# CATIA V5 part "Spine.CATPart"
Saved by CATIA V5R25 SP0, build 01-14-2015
Part number: Part1
Bounding box of the stored display mesh (mm): x 97.05 to 179.832, y -8.213 to 8.213, z -51.727 to 9.114
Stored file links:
  E:\cadcim\GSD_cat_v5-6r2014\Part_files\Spine.CATPart
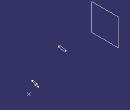
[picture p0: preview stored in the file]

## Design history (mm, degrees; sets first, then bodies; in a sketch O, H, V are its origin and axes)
Body1 (main body)
  Plane1: type Offset, RefPlane yz-plane, Offset 100
  Sketch1 on Plane1, origin (100, 0, 0), H (0, 1, 0), V (0, 0, 1)
    line L1 (-11.8744, 0) -> (18.2844, 0)
    point P1 (-11.8744, 0)
    coincidence: P1 H
    horizontal: L1 H
  Plane2: type Angle, RefPlane Plane1, Direction Sketch1, Angle 30
  Plane3: type Offset, RefPlane Plane2, Offset 75
  Plane4: type Offset, RefPlane Plane3, Offset 20
  Sketch2 on Plane4, origin (157.2724, 0, -90.8013), H (0, 1, 0), V (0.5, 0, 0.866)
    point P1 (0, 45.1194)
    coincidence: P1 V
  Sketch3 on Plane3, origin (139.9519, 0, -80.8013), H (0, 1, 0), V (0.5, 0, 0.866)
    arc A1 centre (0, 54.9362) radius 5.3671 from (5.2994, 54.0869) to (-5.2994, 54.0869) ccw
    point P1 (0, 54.9362)
    arc A2 centre (0, 42.755) radius 3.4394 from (-3.3961, 42.2107) to (3.3961, 42.2107) ccw
    point P2 (0, 42.755)
    line L1 (-5.2994, 54.0869) -> (-3.3961, 42.2107)
    line L2 (5.2994, 54.0869) -> (3.3961, 42.2107)
    coincidence: P1 V, P2 V
    tangency: L1 A1, L1 A2, L2 A1, L2 A2
  Sketch4 on Plane2, origin (75, 0, -43.3013), H (0, 1, 0), V (0.5, 0, 0.866)
    circle A1 centre (0, 52.3122) radius 8.2128
    point P1 (0, 52.3122)
    coincidence: P1 V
